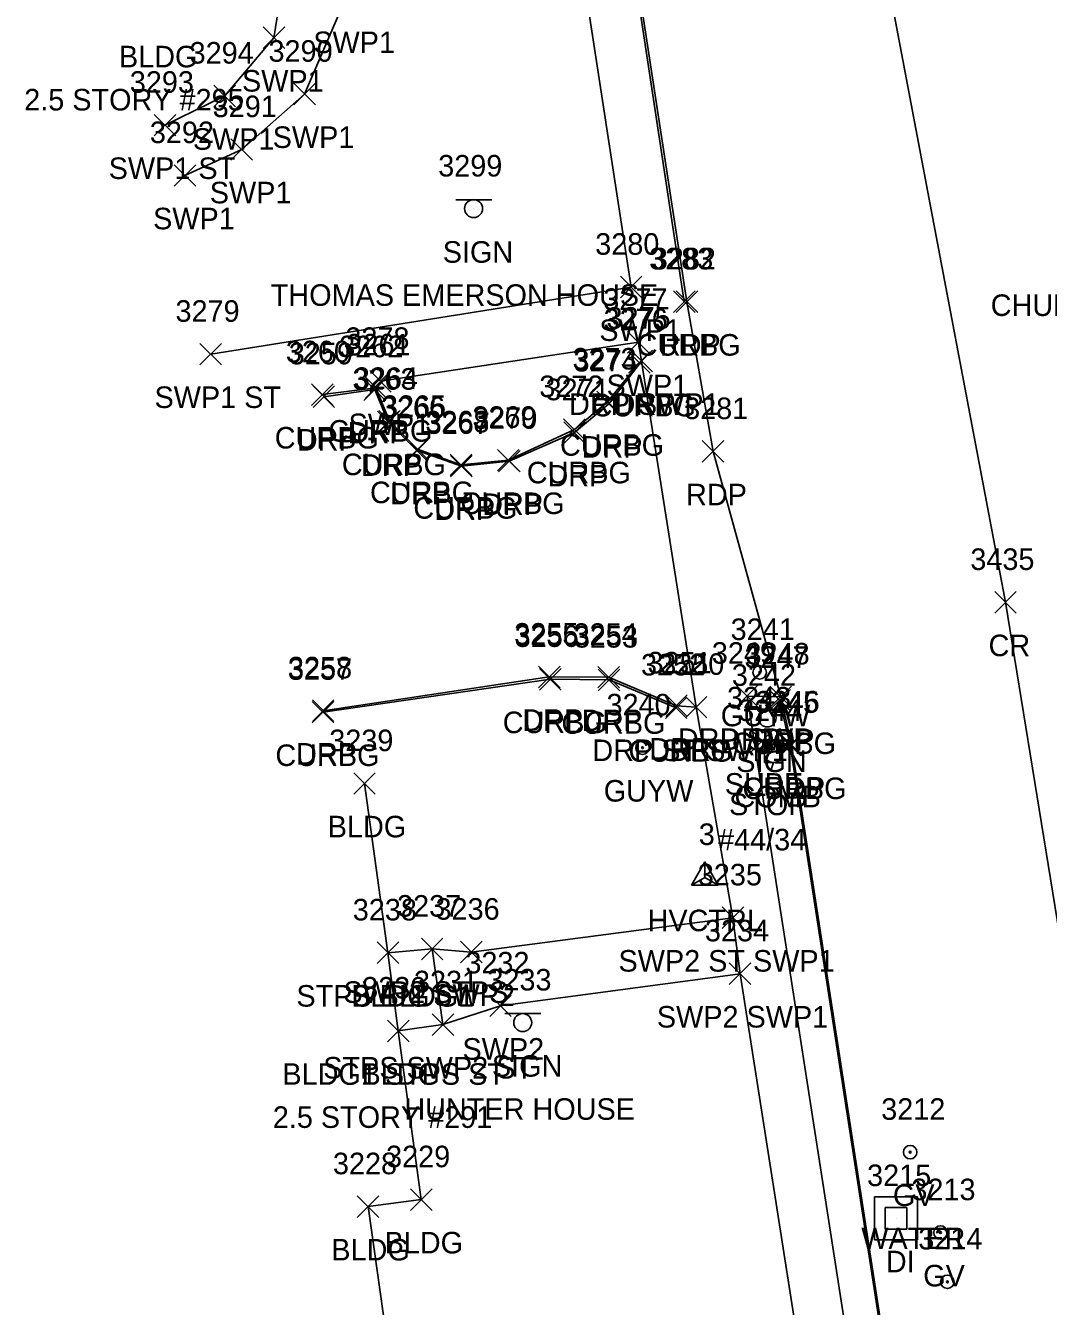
# Model space of a CAD drawing. Extents: x 1690689 to 1696275, y 438760 to 444007.
# Drawn here: x 1691021.5 to 1691116.4, y 442311.5 to 442430.3 of the extents above; entities that cross this region are included whole.
import ezdxf

# ---------------------------------------------------------------- set-up
doc = ezdxf.new("R2010")
doc.units = 0
for name, color, linetype in [('C_A', 7, 'Continuous'), ('C_I', 7, 'Continuous'), ('CPSM', 7, 'Continuous'), ('D_A', 7, 'Continuous'), ('D_I', 7, 'Continuous'), ('DS', 7, 'Continuous'), ('L_A', 7, 'Continuous'), ('L_C', 7, 'Continuous'), ('L_I', 7, 'Continuous'), ('L_TIC', 7, 'Continuous'), ('LBC', 7, 'Continuous'), ('LBF', 7, 'Continuous'), ('P_A', 7, 'Continuous'), ('P_I', 7, 'Continuous'), ('P_TIC', 7, 'Continuous'), ('PET', 7, 'Continuous'), ('PRC', 7, 'Continuous'), ('R_A', 7, 'Continuous'), ('R_I', 7, 'Continuous'), ('R_TIC', 7, 'Continuous'), ('RC', 7, 'Continuous'), ('RDP', 7, 'Continuous'), ('RSW', 7, 'Continuous'), ('S_A', 7, 'Continuous'), ('S_C', 7, 'Continuous'), ('S_I', 7, 'Continuous'), ('SSGN', 7, 'Continuous'), ('U_A', 7, 'Continuous'), ('U_C', 7, 'Continuous'), ('U_I', 7, 'Continuous'), ('U_TIC', 7, 'Continuous'), ('UP', 7, 'Continuous'), ('UPGW', 7, 'Continuous'), ('UWV', 7, 'Continuous')]:
    doc.layers.add(name, color=color, linetype=linetype)

msp = doc.modelspace()

# ---------------------------------------------------------------- linework, layer by layer
at = {"layer": 'CPSM'}
for p, q in [((1691083.28, 442350.59), (1691084.53, 442352.75)), ((1691085.78, 442350.59), (1691084.53, 442352.75)), ((1691084.53, 442351.31), (1691084.53, 442352.75)), ((1691083.28, 442350.59), (1691084.53, 442351.31)), ((1691084.53, 442351.31), (1691084.53, 442351.31)), ((1691084.53, 442351.31), (1691085.78, 442350.59)), ((1691083.28, 442350.59), (1691085.78, 442350.59))]:
    msp.add_line(p, q, dxfattribs=at)
at = {"layer": 'DS'}
for p, q in [((1691100.27, 442321.66), (1691104.27, 442321.66)), ((1691100.27, 442317.66), (1691100.27, 442321.66)), ((1691104.27, 442321.66), (1691104.27, 442317.66)), ((1691101.27, 442318.66), (1691101.27, 442320.66)), ((1691101.27, 442320.66), (1691103.27, 442320.66)), ((1691103.27, 442320.66), (1691103.27, 442318.66)), ((1691102.28, 442319.66), (1691102.28, 442319.66)), ((1691102.28, 442319.66), (1691102.28, 442319.66)), ((1691103.27, 442318.66), (1691101.27, 442318.66)), ((1691104.27, 442317.66), (1691100.27, 442317.66))]:
    msp.add_line(p, q, dxfattribs=at)
at = {"layer": 'L_TIC'}
for points in [[(1691051.95, 442359.02), (1691053.95, 442361.02)], [(1691053.95, 442359.02), (1691051.95, 442361.02)], [(1691054.12, 442343.31), (1691056.12, 442345.31)], [(1691056.12, 442343.31), (1691054.12, 442345.31)], [(1691054.12, 442343.31), (1691056.12, 442345.31)], [(1691056.12, 442343.31), (1691054.12, 442345.31)], [(1691058.23, 442343.66), (1691060.23, 442345.66)], [(1691060.23, 442343.66), (1691058.23, 442345.66)], [(1691059.23, 442336.64), (1691061.23, 442338.64)], [(1691061.23, 442336.64), (1691059.23, 442338.64)], [(1691055.08, 442336.06), (1691057.08, 442338.06)], [(1691057.08, 442336.06), (1691055.08, 442338.06)], [(1691055.08, 442336.06), (1691057.08, 442338.06)], [(1691057.08, 442336.06), (1691055.08, 442338.06)], [(1691052.28, 442319.76), (1691054.28, 442321.76)], [(1691054.28, 442319.76), (1691052.28, 442321.76)], [(1691057.22, 442320.41), (1691059.22, 442322.41)], [(1691059.22, 442320.41), (1691057.22, 442322.41)]]:
    msp.add_lwpolyline(points, dxfattribs=at)
at = {"layer": 'LBC'}
msp.add_lwpolyline([(1691055.53, 442304.92), (1691053.28, 442320.76), (1691058.22, 442321.41), (1691056.08, 442337.06), (1691055.12, 442344.31), (1691052.95, 442360.02)], dxfattribs=at)
at = {"layer": 'LBF'}
msp.add_lwpolyline([(1691056.08, 442337.06), (1691060.23, 442337.64), (1691059.23, 442344.66), (1691055.12, 442344.31)], dxfattribs=at)
at = {"layer": 'P_TIC'}
for points in [[(1691081.87, 442403.72), (1691083.87, 442405.72)], [(1691083.87, 442403.72), (1691081.87, 442405.72)], [(1691084.3, 442389.83), (1691086.3, 442391.83)], [(1691086.3, 442389.83), (1691084.3, 442391.83)], [(1691111.43, 442375.83), (1691113.43, 442377.83)], [(1691113.43, 442375.83), (1691111.43, 442377.83)], [(1691090.57, 442367.06), (1691092.57, 442369.06)], [(1691092.57, 442367.06), (1691090.57, 442369.06)], [(1691091.56, 442362.61), (1691093.56, 442364.61)], [(1691093.56, 442362.61), (1691091.56, 442364.61)]]:
    msp.add_lwpolyline(points, dxfattribs=at)
at = {"layer": 'PET'}
msp.add_lwpolyline([(1691038.8, 442204.16), (1691104.65, 442231.56), (1691109.54, 442233.67), (1691112.1, 442237.28), (1691092.56, 442363.61), (1691091.57, 442368.06), (1691085.3, 442390.83), (1691082.87, 442404.72), (1691074.78, 442457.41), (1691071.06, 442481.04), (1691070.15, 442488.28), (1691067.3, 442505.82), (1691062.5, 442536.43), (1691058.28, 442562.77)], dxfattribs=at)
at = {"layer": 'PRC'}
msp.add_lwpolyline([(1691277.81, 441080.96), (1691253.5, 441214.94), (1691246.19, 441267.52), (1691239.79, 441327.83), (1691235.79, 441375.29), (1691233.27, 441422.2), (1691229.73, 441505.18), (1691226.6, 441557.92), (1691222.02, 441618.83), (1691218.57, 441657.04), (1691144.02, 442182.42), (1691112.43, 442376.83), (1691097.75, 442454.48), (1691089.73, 442499.13), (1691078.44, 442565.84)], dxfattribs=at)
at = {"layer": 'R_TIC'}
for points in [[(1691043.55, 442428.22), (1691045.55, 442430.22)], [(1691045.55, 442428.22), (1691043.55, 442430.22)], [(1691046.39, 442422.99), (1691048.39, 442424.99)], [(1691048.39, 442422.99), (1691046.39, 442424.99)], [(1691038.98, 442422.82), (1691040.98, 442424.82)], [(1691040.98, 442422.82), (1691038.98, 442424.82)], [(1691033.43, 442420.11), (1691035.43, 442422.11)], [(1691035.43, 442420.11), (1691033.43, 442422.11)], [(1691040.55, 442417.85), (1691042.55, 442419.85)], [(1691042.55, 442417.85), (1691040.55, 442419.85)], [(1691035.29, 442415.44), (1691037.29, 442417.44)], [(1691037.29, 442415.44), (1691035.29, 442417.44)], [(1691076.7, 442405.08), (1691078.7, 442407.08)], [(1691078.7, 442405.08), (1691076.7, 442407.08)], [(1691081.62, 442403.72), (1691083.62, 442405.72)], [(1691083.62, 442403.72), (1691081.62, 442405.72)], [(1691077.37, 442399.96), (1691079.37, 442401.96)], [(1691079.37, 442399.96), (1691077.37, 442401.96)], [(1691037.68, 442398.86), (1691039.68, 442400.86)], [(1691039.68, 442398.86), (1691037.68, 442400.86)], [(1691077.46, 442398.08), (1691079.46, 442400.08)], [(1691079.46, 442398.08), (1691077.46, 442400.08)], [(1691077.67, 442398.22), (1691079.67, 442400.22)], [(1691079.67, 442398.22), (1691077.67, 442400.22)], [(1691077.67, 442398.22), (1691079.67, 442400.22)], [(1691079.67, 442398.22), (1691077.67, 442400.22)], [(1691053.01, 442395.74), (1691055.01, 442397.74)], [(1691055.01, 442395.74), (1691053.01, 442397.74)], [(1691053.43, 442396.34), (1691055.43, 442398.34)], [(1691055.43, 442396.34), (1691053.43, 442398.34)], [(1691048.04, 442395.1), (1691050.04, 442397.1)], [(1691050.04, 442395.1), (1691048.04, 442397.1)], [(1691048.18, 442394.91), (1691050.18, 442396.91)], [(1691050.18, 442394.91), (1691048.18, 442396.91)], [(1691052.9, 442395.57), (1691054.9, 442397.57)], [(1691054.9, 442395.57), (1691052.9, 442397.57)], [(1691074.51, 442394.43), (1691076.51, 442396.43)], [(1691076.51, 442394.43), (1691074.51, 442396.43)], [(1691074.61, 442394.25), (1691076.61, 442396.25)], [(1691076.61, 442394.25), (1691074.61, 442396.25)], [(1691054.14, 442392.56), (1691056.14, 442394.56)], [(1691056.14, 442392.56), (1691054.14, 442394.56)], [(1691054.27, 442392.63), (1691056.27, 442394.63)], [(1691056.27, 442392.63), (1691054.27, 442394.63)], [(1691071.43, 442391.87), (1691073.43, 442393.87)], [(1691073.43, 442391.87), (1691071.43, 442393.87)], [(1691071.44, 442391.58), (1691073.44, 442393.58)], [(1691073.44, 442391.58), (1691071.44, 442393.58)], [(1691056.83, 442389.91), (1691058.83, 442391.91)], [(1691058.83, 442389.91), (1691056.83, 442391.91)], [(1691056.88, 442390.03), (1691058.88, 442392.03)], [(1691058.88, 442390.03), (1691056.88, 442392.03)], [(1691060.9, 442388.59), (1691062.9, 442390.59)], [(1691062.9, 442388.59), (1691060.9, 442390.59)], [(1691060.94, 442388.46), (1691062.94, 442390.46)], [(1691062.94, 442388.46), (1691060.94, 442390.46)], [(1691065.28, 442389.02), (1691067.28, 442391.02)], [(1691067.28, 442389.02), (1691065.28, 442391.02)], [(1691065.38, 442388.93), (1691067.38, 442390.93)], [(1691067.38, 442388.93), (1691065.38, 442390.93)], [(1691069.1, 442368.9), (1691071.1, 442370.9)], [(1691071.1, 442368.9), (1691069.1, 442370.9)], [(1691069.2, 442368.69), (1691071.2, 442370.69)], [(1691071.2, 442368.69), (1691069.2, 442370.69)], [(1691074.6, 442368.88), (1691076.6, 442370.88)], [(1691076.6, 442368.88), (1691074.6, 442370.88)], [(1691074.64, 442368.63), (1691076.64, 442370.63)], [(1691076.64, 442368.63), (1691074.64, 442370.63)], [(1691087.45, 442367.13), (1691089.45, 442369.13)], [(1691089.45, 442367.13), (1691087.45, 442369.13)], [(1691087.45, 442367.13), (1691089.45, 442369.13)], [(1691089.45, 442367.13), (1691087.45, 442369.13)], [(1691090.57, 442367.06), (1691092.57, 442369.06)], [(1691092.57, 442367.06), (1691090.57, 442369.06)], [(1691080.87, 442366.04), (1691082.87, 442368.04)], [(1691082.87, 442366.04), (1691080.87, 442368.04)], [(1691080.9, 442366.23), (1691082.9, 442368.23)], [(1691082.9, 442366.23), (1691080.9, 442368.23)], [(1691082.73, 442366.1), (1691084.73, 442368.1)], [(1691084.73, 442366.1), (1691082.73, 442368.1)], [(1691082.73, 442366.1), (1691084.73, 442368.1)], [(1691084.73, 442366.1), (1691082.73, 442368.1)], [(1691090.47, 442366.75), (1691092.47, 442368.75)], [(1691092.47, 442366.75), (1691090.47, 442368.75)], [(1691048.1, 442365.64), (1691050.1, 442367.64)], [(1691050.1, 442365.64), (1691048.1, 442367.64)], [(1691048.11, 442365.77), (1691050.11, 442367.77)], [(1691050.11, 442365.77), (1691048.11, 442367.77)], [(1691091.44, 442362.57), (1691093.44, 442364.57)], [(1691093.44, 442362.57), (1691091.44, 442364.57)], [(1691086.14, 442346.56), (1691088.14, 442348.56)], [(1691088.14, 442346.56), (1691086.14, 442348.56)], [(1691086.14, 442346.56), (1691088.14, 442348.56)], [(1691088.14, 442346.56), (1691086.14, 442348.56)], [(1691058.23, 442343.66), (1691060.23, 442345.66)], [(1691060.23, 442343.66), (1691058.23, 442345.66)], [(1691061.86, 442343.38), (1691063.86, 442345.38)], [(1691063.86, 442343.38), (1691061.86, 442345.38)], [(1691086.8, 442341.37), (1691088.8, 442343.37)], [(1691088.8, 442341.37), (1691086.8, 442343.37)], [(1691086.8, 442341.37), (1691088.8, 442343.37)], [(1691088.8, 442341.37), (1691086.8, 442343.37)], [(1691064.57, 442338.39), (1691066.57, 442340.39)], [(1691066.57, 442338.39), (1691064.57, 442340.39)], [(1691059.23, 442336.64), (1691061.23, 442338.64)], [(1691061.23, 442336.64), (1691059.23, 442338.64)]]:
    msp.add_lwpolyline(points, dxfattribs=at)
at = {"layer": 'RC'}
for points in [[(1691082.62, 442404.72), (1691074.64, 442457.38), (1691070.88, 442481.07)], [(1691049.04, 442396.1), (1691054.01, 442396.74), (1691055.27, 442393.63), (1691057.88, 442391.03), (1691061.9, 442389.59), (1691066.28, 442390.02), (1691072.43, 442392.87), (1691075.51, 442395.43), (1691078.46, 442399.08)], [(1691081.87, 442367.04), (1691075.64, 442369.63), (1691070.2, 442369.69), (1691049.1, 442366.64)], [(1691111.96, 442237.31), (1691092.44, 442363.57), (1691091.47, 442367.75)]]:
    msp.add_lwpolyline(points, dxfattribs=at)
at = {"layer": 'RDP'}
for points in [[(1691049.18, 442395.91), (1691053.9, 442396.57), (1691055.14, 442393.56), (1691057.83, 442390.91), (1691061.94, 442389.46), (1691066.38, 442389.93), (1691072.44, 442392.58), (1691075.61, 442395.25), (1691078.67, 442399.22)], [(1691083.73, 442367.1), (1691081.9, 442367.23), (1691075.6, 442369.88), (1691070.1, 442369.9), (1691049.11, 442366.77)], [(1691091.57, 442368.06), (1691088.45, 442368.13)]]:
    msp.add_lwpolyline(points, dxfattribs=at)
at = {"layer": 'RSW'}
for points in [[(1691038.68, 442399.86), (1691077.7, 442406.08), (1691069.87, 442457.04), (1691050.3, 442453.61), (1691049.27, 442450.47), (1691051.16, 442432.79), (1691047.39, 442423.99), (1691041.55, 442418.85), (1691036.29, 442416.44)], [(1691034.43, 442421.11), (1691039.98, 442423.82), (1691044.55, 442429.22), (1691045.95, 442438.09), (1691044.23, 442450.43), (1691041.74, 442453.05), (1691038.67, 442451)], [(1691035.14, 442213.47), (1691068.76, 442226.99), (1691067.21, 442235.36), (1691072.34, 442236.13), (1691073.32, 442228.73), (1691103.47, 442240.46), (1691099.24, 442268.3), (1691095.25, 442267.82), (1691094.37, 442273.25), (1691098.54, 442273.86), (1691087.8, 442342.37), (1691087.14, 442347.56), (1691083.73, 442367.1), (1691078.67, 442399.22), (1691078.37, 442400.96), (1691054.43, 442397.34)], [(1691108.2, 442241.19), (1691088.45, 442368.13)], [(1691087.14, 442347.56), (1691062.86, 442344.38), (1691059.23, 442344.66)], [(1691060.23, 442337.64), (1691065.57, 442339.39), (1691087.8, 442342.37)]]:
    msp.add_lwpolyline(points, dxfattribs=at)
at = {"layer": 'SSGN'}
for p, q in [((1691061.43, 442414.19), (1691064.76, 442414.19)), ((1691063.07, 442413.36), (1691063.07, 442413.36)), ((1691088.67, 442366.93), (1691092, 442366.93)), ((1691090.32, 442366.1), (1691090.32, 442366.1)), ((1691065.98, 442338.66), (1691069.31, 442338.66)), ((1691067.63, 442337.83), (1691067.63, 442337.83))]:
    msp.add_line(p, q, dxfattribs=at)
for centre in [(1691063.07, 442413.36), (1691090.32, 442366.1), (1691067.63, 442337.83)]:
    msp.add_circle(centre, 0.833, dxfattribs=at)
at = {"layer": 'U_TIC'}
for points in [[(1691088.85, 442362.98), (1691090.85, 442364.98)], [(1691090.85, 442362.98), (1691088.85, 442364.98)]]:
    msp.add_lwpolyline(points, dxfattribs=at)
at = {"layer": 'UP'}
for p, q in [((1691091.14, 442364.47), (1691090.89, 442363.64)), ((1691090.06, 442361.97), (1691090.06, 442363.64)), ((1691090.06, 442363.64), (1691091.73, 442363.64)), ((1691091.73, 442363.64), (1691091.73, 442361.97)), ((1691091.73, 442361.97), (1691090.06, 442361.97)), ((1691090.64, 442361.14), (1691090.89, 442361.97)), ((1691090.89, 442362.81), (1691090.89, 442362.81))]:
    msp.add_line(p, q, dxfattribs=at)
msp.add_circle((1691090.89, 442362.81), 0.833, dxfattribs=at)
at = {"layer": 'UPGW'}
for centre, radius in [((1691089.62, 442370.33), 0.625), ((1691089.62, 442370.33), 0.0833), ((1691078.75, 442363.34), 0.625), ((1691078.75, 442363.34), 0.0833)]:
    msp.add_circle(centre, radius, dxfattribs=at)
at = {"layer": 'UWV'}
for centre, radius in [((1691103.59, 442325.81), 0.625), ((1691103.59, 442325.81), 0.0833), ((1691106.4, 442318.35), 0.625), ((1691106.4, 442318.35), 0.0833), ((1691107.04, 442313.78), 0.625), ((1691107.04, 442313.78), 0.0833)]:
    msp.add_circle(centre, radius, dxfattribs=at)

# ---------------------------------------------------------------- texts
at = {"layer": 'C_A'}
msp.add_text('HVCTRL', height=2, dxfattribs=at).set_placement((1691079.22, 442346.31))
at = {"layer": 'C_I'}
msp.add_text('3', height=2, dxfattribs=at).set_placement((1691083.97, 442354.31))
at = {"layer": 'D_A'}
msp.add_text('DI', height=2, dxfattribs=at).set_placement((1691101.33, 442314.66))
at = {"layer": 'D_I'}
msp.add_text('3215', height=2, dxfattribs=at).set_placement((1691099.59, 442322.66))
at = {"layer": 'L_A'}
for s, p in [('BLDG', (1691030.16, 442426.47)), ('BLDG', (1691049.54, 442355.02)), ('STPS BLDG1', (1691046.63, 442339.31)), ('SWP2 STPS', (1691050.99, 442339.66)), ('BLDG', (1691051.71, 442339.31)), ('STPS SWP2 ST', (1691049.12, 442332.64)), ('BLDG1 STPS ST', (1691045.33, 442332.06)), ('BLDG', (1691052.67, 442332.06)), ('BLDG', (1691054.81, 442316.41)), ('BLDG', (1691049.87, 442315.76))]:
    msp.add_text(s, height=2, dxfattribs=at).set_placement(p)
at = {"layer": 'L_C'}
for s, p in [('2.5 STORY #295', (1691021.37, 442422.47)), ('2.5 STORY #291', (1691044.44, 442328.06))]:
    msp.add_text(s, height=2, dxfattribs=at).set_placement(p)
at = {"layer": 'L_I'}
for s, p in [('3239', (1691049.68, 442363.02)), ('3238', (1691051.86, 442347.31)), ('3238', (1691051.86, 442347.31)), ('3237', (1691055.97, 442347.66)), ('3230', (1691052.73, 442340.06)), ('3230', (1691052.73, 442340.06)), ('3231', (1691057.54, 442340.64)), ('3229', (1691054.95, 442324.41)), ('3228', (1691050.02, 442323.76))]:
    msp.add_text(s, height=2, dxfattribs=at).set_placement(p)
at = {"layer": 'P_A'}
for s, p in [('RDP', (1691080.36, 442399.72)), ('RDP', (1691082.79, 442385.83)), ('CR', (1691110.86, 442371.83)), ('RDP', (1691089.06, 442363.06)), ('RDP', (1691090.05, 442358.61))]:
    msp.add_text(s, height=2, dxfattribs=at).set_placement(p)
at = {"layer": 'P_I'}
for s, p in [('3282', (1691079.61, 442407.72)), ('3281', (1691082.61, 442393.83)), ('3435', (1691109.17, 442379.83)), ('3248', (1691088.31, 442371.06)), ('3246', (1691089.25, 442366.61))]:
    msp.add_text(s, height=2, dxfattribs=at).set_placement(p)
at = {"layer": 'R_A'}
for s, p in [('SWP1', (1691048.2, 442427.79)), ('SWP1', (1691041.58, 442424.22)), ('SWP1', (1691037.02, 442418.82)), ('SWP1', (1691044.43, 442418.99)), ('SWP1 ST', (1691029.21, 442416.11)), ('SWP1', (1691038.59, 442413.85)), ('SWP1', (1691033.33, 442411.44)), ('SWP1', (1691074.74, 442401.08)), ('CURBG', (1691078.2, 442399.72)), ('SWP1', (1691075.41, 442395.96)), ('SWP1 ST', (1691033.46, 442394.86)), ('DRP SWP1', (1691071.93, 442394.22)), ('CURBG', (1691074.04, 442394.08)), ('DRP', (1691076.16, 442394.22)), ('SWP1', (1691051.47, 442392.34)), ('CURBG', (1691044.62, 442391.1)), ('DRP', (1691046.67, 442390.91)), ('CURBG', (1691049.59, 442391.74)), ('DRP', (1691051.39, 442391.57)), ('CURBG', (1691071.09, 442390.43)), ('DRP', (1691073.1, 442390.25)), ('CURBG', (1691050.85, 442388.63)), ('DRP', (1691052.62, 442388.56)), ('CURBG', (1691068.01, 442387.87)), ('DRP', (1691069.93, 442387.58)), ('CURBG', (1691053.46, 442386.03)), ('DRP', (1691055.32, 442385.91)), ('CURBG', (1691061.86, 442385.02)), ('DRP', (1691063.87, 442384.93)), ('CURBG', (1691057.48, 442384.59)), ('DRP', (1691059.43, 442384.46)), ('CURBG', (1691065.78, 442364.69)), ('DRP', (1691067.59, 442364.9)), ('DRP', (1691073.09, 442364.88)), ('CURBG', (1691071.22, 442364.63)), ('DRP SWP', (1691082.03, 442363.13)), ('DRP', (1691085.94, 442363.13)), ('CURBG', (1691087.05, 442362.75)), ('DRP', (1691089.06, 442363.06)), ('CURBG', (1691044.68, 442361.64)), ('DRP', (1691046.6, 442361.77)), ('DRP ST SWP1', (1691074.1, 442362.1)), ('CURBG', (1691077.45, 442362.04)), ('DRP', (1691079.39, 442362.23)), ('DRP', (1691081.22, 442362.1)), ('CURBG', (1691088.02, 442358.57)), ('SWP2 ST SWP1', (1691076.52, 442342.56)), ('SWP2 ST SWP1', (1691076.52, 442342.56)), ('SWP2 STPS', (1691050.99, 442339.66)), ('SWP2', (1691059.33, 442339.38)), ('SWP2 SWP1', (1691080.08, 442337.37)), ('SWP2 SWP1', (1691080.08, 442337.37)), ('SWP2', (1691062.04, 442334.39)), ('STPS SWP2 ST', (1691049.12, 442332.64))]:
    msp.add_text(s, height=2, dxfattribs=at).set_placement(p)
at = {"layer": 'R_I'}
for s, p in [('3294', (1691036.72, 442426.82)), ('3290', (1691044.04, 442426.99)), ('3293', (1691031.17, 442424.11)), ('3291', (1691038.86, 442421.85)), ('3292', (1691033.03, 442419.44)), ('3280', (1691074.36, 442409.08)), ('3283', (1691079.36, 442407.72)), ('3277', (1691075.11, 442403.96)), ('3279', (1691035.41, 442402.86)), ('3276', (1691075.14, 442402.08)), ('3275', (1691075.41, 442402.22)), ('3275', (1691075.41, 442402.22)), ('3278', (1691051.17, 442400.34)), ('3262', (1691050.6, 442399.57)), ('3261', (1691051.27, 442399.74)), ('3260', (1691045.65, 442399.1)), ('3259', (1691045.92, 442398.91)), ('3273', (1691072.25, 442398.43)), ('3274', (1691072.35, 442398.25)), ('3263', (1691051.83, 442396.56)), ('3264', (1691051.96, 442396.63)), ('3272', (1691069.17, 442395.87)), ('3271', (1691069.75, 442395.58)), ('3266', (1691054.47, 442393.91)), ('3265', (1691054.57, 442394.03)), ('3268', (1691058.59, 442392.59)), ('3267', (1691058.63, 442392.46)), ('3269', (1691062.96, 442393.02)), ('3270', (1691063.03, 442392.93)), ('3255', (1691066.84, 442372.9)), ('3256', (1691066.89, 442372.69)), ('3254', (1691072.34, 442372.88)), ('3253', (1691072.38, 442372.63)), ('3249', (1691085.18, 442371.13)), ('3249', (1691085.18, 442371.13)), ('3247', (1691088.21, 442370.75)), ('3248', (1691088.31, 442371.06)), ('3257', (1691045.84, 442369.64)), ('3258', (1691045.85, 442369.77)), ('3252', (1691078.61, 442370.04)), ('3251', (1691079.21, 442370.23)), ('3250', (1691080.39, 442370.1)), ('3250', (1691080.39, 442370.1)), ('3245', (1691089.18, 442366.57)), ('3235', (1691083.88, 442350.56)), ('3235', (1691083.88, 442350.56)), ('3237', (1691055.97, 442347.66)), ('3236', (1691059.54, 442347.38)), ('3234', (1691084.54, 442345.37)), ('3234', (1691084.54, 442345.37)), ('3232', (1691062.31, 442342.39)), ('3231', (1691057.54, 442340.64))]:
    msp.add_text(s, height=2, dxfattribs=at).set_placement(p)
at = {"layer": 'S_A'}
for p in [(1691060.21, 442408.34), (1691087.45, 442361.08), (1691064.77, 442332.81)]:
    msp.add_text('SIGN', height=2, dxfattribs=at).set_placement(p)
at = {"layer": 'S_C'}
for s, p in [('THOMAS EMERSON HOUSE', (1691044.25, 442404.34)), ('CHURCH ST/MAIN ST', (1691111.06, 442403.4)), ('STOP', (1691086.78, 442357.08)), ('HUNTER HOUSE', (1691056.65, 442328.81))]:
    msp.add_text(s, height=2, dxfattribs=at).set_placement(p)
at = {"layer": 'S_I'}
for s, p in [('3299', (1691059.79, 442416.34)), ('3242', (1691087.04, 442369.08)), ('3233', (1691064.35, 442340.81))]:
    msp.add_text(s, height=2, dxfattribs=at).set_placement(p)
at = {"layer": 'U_A'}
for s, p in [('GUYW', (1691086.01, 442365.33)), ('SUBE', (1691086.38, 442358.98)), ('GUYW', (1691075.15, 442358.34)), ('COMB', (1691087.28, 442357.81)), ('GV', (1691101.99, 442320.81)), ('GV', (1691104.8, 442313.35))]:
    msp.add_text(s, height=2, dxfattribs=at).set_placement(p)
at = {"layer": 'U_C'}
for s, p in [('#44/34', (1691085.76, 442353.81)), ('WATER', (1691099.05, 442316.81))]:
    msp.add_text(s, height=2, dxfattribs=at).set_placement(p)
at = {"layer": 'U_I'}
for s, p in [('3241', (1691086.93, 442373.33)), ('3240', (1691075.41, 442366.34)), ('3243', (1691086.59, 442366.98)), ('3244', (1691087.63, 442365.81)), ('3212', (1691100.9, 442328.81)), ('3213', (1691103.7, 442321.35)), ('3214', (1691104.34, 442316.78))]:
    msp.add_text(s, height=2, dxfattribs=at).set_placement(p)

doc.saveas('drawing.dxf')
